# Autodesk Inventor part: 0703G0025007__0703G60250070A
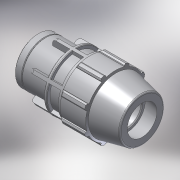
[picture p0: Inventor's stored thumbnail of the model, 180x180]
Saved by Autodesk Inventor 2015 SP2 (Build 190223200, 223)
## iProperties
Created: 2017-02
Part Number: 0703G0025007__0703G60250070A
Material: PVC-Piping
Description: PLASSON FEMALE ADAPTOR G 25-3/4"
Document SubType Name: Modeling
Designer: KIM
Mass: 92.6774 g
Surface Area: 199.44 cm^2
Volume: 66.1981 cm^3
Density: 1.4 g/cm^3
Appearance: Smooth - White
Author: KIM
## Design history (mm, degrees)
derived "0703G0.ipt"
feature "Solid1::0703G0.ipt"
tag "TaggingFeature1"
body "Solid1"
other parameters: "d2" = 25, "d4" = 12.57143, "d5" = 22, "d7" = 54, "d9" = 12.57143, "d11" = 2.51429, "d12" = 43.2, "d13" = 120 deg, "d14" = 37.5, "d15" = 12 deg, "d16" = 48.6, "d18" = 1.25, "d19" = 35 deg, "d20" = 17.5 deg, "d21" = 50.22, "d23" = 0, "d25" = 360 deg, "d27" = 1.08, "d34" = 2.7, "d35" = 26.4, "d36" = 0, "d42" = 22, "d43" = 1.62, "d46" = 0.75, "d49" = 63, "d51" = 88, "d53" = 0.5, "d55" = 360 deg, "d61" = 12, "d63" = 24.117, "d64" = 29.33333, "d65" = 2.7, "d66" = 0.5, "d67" = 1, "d68" = 6, "d69" = 38.88, "d_" = 25, "E_" = 54, "H_" = 88, "l_" = 63, "l_2" = 12, "Rp_" = 24.117
